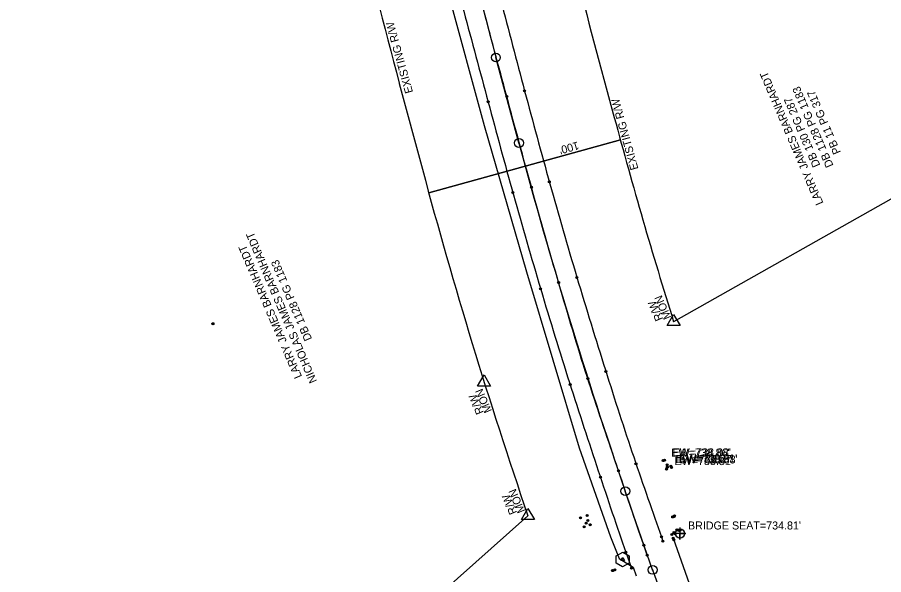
# Model space of a CAD drawing. Extents: x 1550153 to 1552579, y 809637 to 812160.
# Drawn here: x 1551459.6 to 1551894.8, y 810857.2 to 811136.9 of the extents above; entities that cross this region are included whole.
import ezdxf

# ---------------------------------------------------------------- set-up
doc = ezdxf.new("R2010")
doc.units = 0
for name, color, linetype in [('CTL Primary Horizontal and Vertical CELL', 7, 'Continuous'), ('Default', 7, 'Continuous'), ('E_NCDOT_Horizontal_Alignment', 7, 'Continuous'), ('E_NCDOT_Horizontal_Alignment_Curve', 7, 'Continuous'), ('E_NCDOT_Horizontal_Alignment_Tick_Label', 7, 'Continuous'), ('Exist DTM Crownline', 7, 'Continuous'), ('Exist Property Text', 7, 'Continuous'), ('Exist Right of Way Line', 7, 'Continuous'), ('Exist Right of Way Line Leader', 7, 'Continuous'), ('Exist Right of Way Line Text', 7, 'Continuous'), ('Exist Right of Way Monument CELL', 7, 'Continuous'), ('Exist Right of Way Monument Text', 7, 'Continuous'), ('Exist Roads EOP', 7, 'Continuous'), ('Exist Roads EOP Other', 7, 'Continuous'), ('Exist Structure Major Bridge Seat Cogo Point CELL', 7, 'Continuous'), ('Exist Structure Minor Head and End Wall', 7, 'Continuous'), ('Exist Survey Control Group', 7, 'Continuous'), ('Exist Utilities Telephone UG Cable SUE LOS B', 7, 'Continuous')]:
    doc.layers.add(name, color=color, linetype=linetype)

# ---------------------------------------------------------------- blocks, each defined once
blk = doc.blocks.new('SurveyPointCell')
at = {"layer": 'Default'}
for p, q in [((-0.5, 0), (0.5, 0)), ((0, -0.5), (0, 0.5))]:
    blk.add_line(p, q, dxfattribs=at)
blk.add_circle((0, 0), 0.5, dxfattribs=at)
blk = doc.blocks.new('SurveyControlPointCell')
at = {"layer": 'Default'}
for p, q in [((-0.87, -0.5), (0, 1)), ((0, 1), (0.87, -0.5)), ((0.87, -0.5), (-0.87, -0.5))]:
    blk.add_line(p, q, dxfattribs=at)
blk.add_circle((0, 0), 0.5, dxfattribs=at)

msp = doc.modelspace()

# ---------------------------------------------------------------- linework, layer by layer
at = {"layer": 'CTL Primary Horizontal and Vertical CELL'}
msp.add_line((1551763.72, 810864.75), (1551763.72, 810864.75), dxfattribs=at)
msp.add_line((1551763.72, 810864.75), (1551763.72, 810864.75), dxfattribs=at)
msp.add_line((1551763.72, 810864.75), (1551763.72, 810864.75), dxfattribs=at)
msp.add_lwpolyline([(1551760.49, 810866.62), (1551763.74, 810868.43), (1551766.99, 810866.65), (1551766.94, 810862.92), (1551763.69, 810861.03), (1551760.49, 810862.85)], close=True, dxfattribs=at)
msp.add_lwpolyline([(1551760.49, 810866.62), (1551763.74, 810868.43), (1551766.99, 810866.65), (1551766.94, 810862.92), (1551763.69, 810861.03), (1551760.49, 810862.85)], close=True, dxfattribs=at)
msp.add_lwpolyline([(1551760.49, 810866.62), (1551763.74, 810868.43), (1551766.99, 810866.65), (1551766.94, 810862.92), (1551763.69, 810861.03), (1551760.49, 810862.85)], close=True, dxfattribs=at)
at = {"layer": 'Default'}
for p, q in [((1551792.49, 810877.81), (1551792.49, 810877.81)), ((1551763.72, 810864.75), (1551763.72, 810864.75))]:
    msp.add_line(p, q, dxfattribs=at)
msp.add_arc((1544558.52, 818987.58), 11000, 308.905285, 313.48368, dxfattribs=at)
msp.add_arc((1544558.52, 818987.58), 11000, 308.905285, 313.48368, dxfattribs=at)
at = {"layer": 'E_NCDOT_Horizontal_Alignment'}
for p, q in [((1551711.61, 811073.81), (1551700.02, 811116.69)), ((1551778.76, 810859.54), (1551765.03, 810899.04))]:
    msp.add_line(p, q, dxfattribs=at)
for centre, radius in [((1551700.02, 811116.69), 2.2), ((1551700.02, 811116.69), 0.0707), ((1551711.61, 811073.81), 2.2), ((1551711.61, 811073.81), 0.0707), ((1551765.03, 810899.04), 2.2), ((1551765.03, 810899.04), 0.0707), ((1551778.76, 810859.54), 2.2), ((1551778.76, 810859.54), 0.0707)]:
    msp.add_circle(centre, radius, dxfattribs=at)
at = {"layer": 'E_NCDOT_Horizontal_Alignment_Curve'}
for centre, radius, start, end in [((1571051.3, 816169.19), 20000, 194.057496, 194.632887), ((1571051.3, 816169.19), 20000, 194.057496, 194.632887), ((1554271.06, 811760.59), 2650, 195.02047, 198.97242), ((1554271.06, 811760.59), 2650, 195.02047, 198.97242), ((1544245.73, 819324.67), 11459.16, 307.933611, 313.133611), ((1544245.73, 819324.67), 11459.16, 307.933611, 313.133611), ((1554277.17, 811742.97), 2650, 199.47344, 205.4841), ((1554277.17, 811742.97), 2650, 199.47344, 205.4841)]:
    msp.add_arc(centre, radius, start, end, dxfattribs=at)
at = {"layer": 'E_NCDOT_Horizontal_Alignment_Tick_Label'}
msp.add_arc((1544558.52, 818987.58), 11000, 308.905285, 313.48368, dxfattribs=at)
at = {"layer": 'Exist DTM Crownline'}
msp.add_line((1551775.98, 810866.94), (1551774.27, 810871.88), dxfattribs=at)
msp.add_line((1551775.98, 810866.94), (1551774.27, 810871.88), dxfattribs=at)
msp.add_open_spline([(1551774.27, 810871.88), (1551769.96, 810884.28), (1551760.75, 810912.22), (1551745.66, 810955.91), (1551731.5, 811003.54), (1551718, 811050.78), (1551705.43, 811097.26), (1551693.24, 811142.67), (1551681.43, 811187.98), (1551670.2, 811231.95), (1551663.06, 811260.98), (1551659.56, 811274.89)], degree=3, dxfattribs=at)
msp.add_open_spline([(1551774.27, 810871.88), (1551769.96, 810884.28), (1551760.75, 810912.22), (1551745.66, 810955.91), (1551731.5, 811003.54), (1551718, 811050.78), (1551705.43, 811097.26), (1551693.24, 811142.67), (1551681.43, 811187.98), (1551670.2, 811231.95), (1551663.06, 811260.98), (1551659.56, 811274.89)], degree=3, dxfattribs=at)
at = {"layer": 'Exist Right of Way Line'}
for p, q in [((1551965.65, 811083.67), (1551789.31, 810984.03)), ((1551716.1, 810886.69), (1551186.17, 810416.44))]:
    msp.add_line(p, q, dxfattribs=at)
for points in [[(1551747.95, 811129.4), (1551759.49, 811086.68), (1551759.5, 811086.64)], [(1551651.41, 811103.86), (1551651.46, 811103.65), (1551663.1, 811060.6)]]:
    msp.add_lwpolyline(points, dxfattribs=at)
for centre, radius, start, end in [((1571051.08, 816168.98), 20050, 194.120183, 194.632887), ((1571050.91, 816169.06), 19950, 194.207218, 194.632275), ((1554270.67, 811760.47), 2600, 195.02047, 197.37538), ((1554270.83, 811760.39), 2700, 195.02141, 198.88035)]:
    msp.add_arc(centre, radius, start, end, dxfattribs=at)
at = {"layer": 'Exist Right of Way Line Leader'}
for p, q in [((1551666.29, 811048.77), (1551762.55, 811075.38)), ((1551762.55, 811075.38), (1551666.29, 811048.77))]:
    msp.add_line(p, q, dxfattribs=at)
at = {"layer": 'Exist Right of Way Monument CELL'}
for p, q in [((1551789.31, 810984.03), (1551789.31, 810984.03)), ((1551789.31, 810984.03), (1551789.31, 810984.03)), ((1551694.04, 810953.63), (1551694.04, 810953.63)), ((1551694.04, 810953.63), (1551694.04, 810953.63)), ((1551716.1, 810886.69), (1551716.1, 810886.69)), ((1551716.1, 810886.69), (1551716.1, 810886.69))]:
    msp.add_line(p, q, dxfattribs=at)
for points in [[(1551786.06, 810982.14), (1551789.31, 810987.78), (1551792.56, 810982.14)], [(1551786.06, 810982.14), (1551789.31, 810987.78), (1551792.56, 810982.14)], [(1551690.79, 810951.74), (1551694.04, 810957.38), (1551697.29, 810951.74)], [(1551690.79, 810951.74), (1551694.04, 810957.38), (1551697.29, 810951.74)], [(1551712.86, 810884.8), (1551716.11, 810890.44), (1551719.35, 810884.8)], [(1551712.86, 810884.8), (1551716.11, 810890.44), (1551719.35, 810884.8)]]:
    msp.add_lwpolyline(points, close=True, dxfattribs=at)
at = {"layer": 'Exist Roads EOP'}
for p, q in [((1551783.17, 810876.09), (1551783.92, 810873.92)), ((1551783.17, 810876.09), (1551783.92, 810873.92)), ((1551765.29, 810868.44), (1551768.13, 810860.38)), ((1551765.29, 810868.44), (1551768.13, 810860.38))]:
    msp.add_line(p, q, dxfattribs=at)
for points in [[(1551669.23, 811277), (1551672.74, 811263.65), (1551679.61, 811234.96), (1551690.37, 811191.22), (1551702.41, 811145.66), (1551714.33, 811100.03), (1551727, 811053.46), (1551740.47, 811006.5), (1551755.13, 810959.34), (1551769.1, 810915.85), (1551778.93, 810888.33), (1551783.17, 810876.09)], [(1551669.23, 811277), (1551672.74, 811263.65), (1551679.61, 811234.96), (1551690.37, 811191.22), (1551702.41, 811145.66), (1551714.33, 811100.03), (1551727, 811053.46), (1551740.47, 811006.5), (1551755.13, 810959.34), (1551769.1, 810915.85), (1551778.93, 810888.33), (1551783.17, 810876.09)], [(1551650.09, 811272.18), (1551653.54, 811258.38), (1551661.25, 811229.54), (1551671.78, 811185.41), (1551683.85, 811140.03), (1551696.07, 811094.57), (1551708.62, 811047.91), (1551722.36, 811000.57), (1551736.98, 810952.93), (1551751.55, 810908.96), (1551760.88, 810880.93), (1551765.29, 810868.44)], [(1551650.09, 811272.18), (1551653.54, 811258.38), (1551661.25, 811229.54), (1551671.78, 811185.41), (1551683.85, 811140.03), (1551696.07, 811094.57), (1551708.62, 811047.91), (1551722.36, 811000.57), (1551736.98, 810952.93), (1551751.55, 810908.96), (1551760.88, 810880.93), (1551765.29, 810868.44)]]:
    msp.add_open_spline(points, degree=3, dxfattribs=at)
at = {"layer": 'Exist Roads EOP Other'}
msp.add_line((1551789.07, 810875.41), (1551799.93, 810844.99), dxfattribs=at)
msp.add_line((1551789.07, 810875.41), (1551799.93, 810844.99), dxfattribs=at)
at = {"layer": 'Exist Structure Major Bridge Seat Cogo Point CELL'}
msp.add_lwpolyline([(1551792.49, 810880.81), (1551792.49, 810874.81), (1551792.49, 810877.81), (1551795.49, 810877.81), (1551789.49, 810877.81)], dxfattribs=at)
msp.add_circle((1551792.49, 810877.81), 2.34, dxfattribs=at)
at = {"layer": 'Exist Survey Control Group'}
msp.add_line((1551763.72, 810864.75), (1551763.72, 810864.75), dxfattribs=at)
msp.add_lwpolyline([(1551762.85, 810864.25), (1551763.72, 810865.75), (1551764.58, 810864.25)], close=True, dxfattribs=at)
msp.add_circle((1551763.72, 810864.75), 0.5, dxfattribs=at)
at = {"layer": 'Exist Utilities Telephone UG Cable SUE LOS B'}
msp.add_lwpolyline([(1551635.47, 811205.41), (1551654.84, 811204.95), (1551659.43, 811203.7), (1551662.57, 811201.11), (1551675.9, 811149.68), (1551694.16, 811082.62), (1551715.46, 811009.19), (1551741.91, 810920.73), (1551757.61, 810876.2), (1551761.94, 810865.34), (1551769.04, 810860.85), (1551770.5, 810856.61)], dxfattribs=at)

# ---------------------------------------------------------------- block references
at = {"layer": 'Default'}
for name, p in [('SurveyPointCell', (1551705.47, 811097.19)), ('SurveyPointCell', (1551705.47, 811097.19)), ('SurveyPointCell', (1551714.44, 811099.93)), ('SurveyPointCell', (1551714.44, 811099.93)), ('SurveyPointCell', (1551696.08, 811094.54)), ('SurveyPointCell', (1551696.08, 811094.54)), ('SurveyPointCell', (1551726.86, 811054.37)), ('SurveyPointCell', (1551726.86, 811054.37)), ('SurveyPointCell', (1551708.51, 811048.9)), ('SurveyPointCell', (1551708.51, 811048.9)), ('SurveyPointCell', (1551717.87, 811051.66)), ('SurveyPointCell', (1551717.87, 811051.66)), ('SurveyPointCell', (1551740.71, 811006.35)), ('SurveyPointCell', (1551740.71, 811006.35)), ('SurveyPointCell', (1551722.47, 811000.64)), ('SurveyPointCell', (1551722.47, 811000.64)), ('SurveyPointCell', (1551731.53, 811003.74)), ('SurveyPointCell', (1551731.53, 811003.74)), ('SurveyPointCell', (1551557.89, 810983.12)), ('SurveyPointCell', (1551557.89, 810983.12)), ('SurveyPointCell', (1551755.26, 810959.19)), ('SurveyPointCell', (1551755.26, 810959.19)), ('SurveyPointCell', (1551737.3, 810952.53)), ('SurveyPointCell', (1551737.3, 810952.53)), ('SurveyPointCell', (1551746.16, 810955.54)), ('SurveyPointCell', (1551746.16, 810955.54)), ('SurveyPointCell', (1551784.09, 810914.38)), ('SurveyPointCell', (1551784.09, 810914.38)), ('SurveyPointCell', (1551784.74, 810914.55)), ('SurveyPointCell', (1551784.74, 810914.55)), ('SurveyPointCell', (1551761.66, 810909.21)), ('SurveyPointCell', (1551761.66, 810909.21)), ('SurveyPointCell', (1551770.39, 810912.78)), ('SurveyPointCell', (1551770.39, 810912.78)), ('SurveyPointCell', (1551785.74, 810910.15)), ('SurveyPointCell', (1551785.74, 810910.15)), ('SurveyPointCell', (1551786.05, 810912.31)), ('SurveyPointCell', (1551786.05, 810912.31)), ('SurveyPointCell', (1551786.12, 810911.12)), ('SurveyPointCell', (1551786.12, 810911.12)), ('SurveyPointCell', (1551787.94, 810911.59)), ('SurveyPointCell', (1551787.94, 810911.59)), ('SurveyPointCell', (1551788.17, 810910.96)), ('SurveyPointCell', (1551788.17, 810910.96)), ('SurveyPointCell', (1551752.52, 810906.06)), ('SurveyPointCell', (1551752.52, 810906.06)), ('SurveyPointCell', (1551745.83, 810886.87)), ('SurveyPointCell', (1551745.83, 810886.87)), ('SurveyPointCell', (1551742.47, 810885.7)), ('SurveyPointCell', (1551742.47, 810885.7)), ('SurveyPointCell', (1551745.35, 810883.06)), ('SurveyPointCell', (1551745.35, 810883.06)), ('SurveyPointCell', (1551746.14, 810884.32)), ('SurveyPointCell', (1551746.14, 810884.32)), ('SurveyPointCell', (1551788.83, 810886.11)), ('SurveyPointCell', (1551788.83, 810886.11)), ('SurveyPointCell', (1551789.49, 810886.35)), ('SurveyPointCell', (1551789.49, 810886.35)), ('SurveyPointCell', (1551789.72, 810886.68)), ('SurveyPointCell', (1551789.72, 810886.68)), ('SurveyPointCell', (1551744.32, 810881.11)), ('SurveyPointCell', (1551744.32, 810881.11)), ('SurveyPointCell', (1551747.39, 810882.23)), ('SurveyPointCell', (1551747.39, 810882.23)), ('SurveyPointCell', (1551789.5, 810878.31)), ('SurveyPointCell', (1551789.5, 810878.31)), ('SurveyPointCell', (1551790.96, 810879.6)), ('SurveyPointCell', (1551790.96, 810879.6)), ('SurveyPointCell', (1551791.97, 810879.37)), ('SurveyPointCell', (1551791.97, 810879.37)), ('SurveyPointCell', (1551792.5, 810879.49)), ('SurveyPointCell', (1551792.5, 810879.49)), ('SurveyPointCell', (1551783.17, 810876.09)), ('SurveyPointCell', (1551783.17, 810876.09)), ('SurveyPointCell', (1551783.92, 810873.92)), ('SurveyPointCell', (1551783.92, 810873.92)), ('SurveyPointCell', (1551788.44, 810877.26)), ('SurveyPointCell', (1551788.44, 810877.26)), ('SurveyPointCell', (1551789.07, 810875.41)), ('SurveyPointCell', (1551789.07, 810875.41)), ('SurveyPointCell', (1551789.38, 810874.58)), ('SurveyPointCell', (1551789.38, 810874.58)), ('SurveyPointCell', (1551790.09, 810877.72)), ('SurveyPointCell', (1551790.09, 810877.72)), ('SurveyPointCell', (1551774.27, 810871.88)), ('SurveyPointCell', (1551774.27, 810871.88)), ('SurveyControlPointCell', (1551763.72, 810864.75)), ('SurveyControlPointCell', (1551763.72, 810864.75)), ('SurveyPointCell', (1551765.29, 810868.44)), ('SurveyPointCell', (1551765.29, 810868.44)), ('SurveyPointCell', (1551775.98, 810866.94)), ('SurveyPointCell', (1551775.98, 810866.94)), ('SurveyPointCell', (1551758.54, 810859.17)), ('SurveyPointCell', (1551758.54, 810859.17)), ('SurveyPointCell', (1551758.96, 810859.29)), ('SurveyPointCell', (1551758.96, 810859.29)), ('SurveyPointCell', (1551759.76, 810859.53)), ('SurveyPointCell', (1551759.76, 810859.53)), ('SurveyPointCell', (1551768.13, 810860.38)), ('SurveyPointCell', (1551768.13, 810860.38))]:
    msp.add_blockref(name, p, dxfattribs=at)

# ---------------------------------------------------------------- texts
msp.add_text("BRIDGE SEAT=734.81'", height=4.02, dxfattribs=at).set_placement((1551796.51, 810879.82))
at = {"layer": 'Exist Property Text'}
for s, p in [('LARRY JAMES BARNHARDT', (1551864.63, 811043.64)), ('DB 1128 PG 1183', (1551869.67, 811062.51)), ('PB 11 PG 317', (1551873.39, 811069.14)), ('DB 130 PG 287', (1551863.06, 811062.63)), ('NICHOLAS JAMES BARNHARDT', (1551610.25, 810954.29)), ('LARRY JAMES BARNHARDT', (1551602.7, 810956.6)), ('DB 1128 PG 1183', (1551607.74, 810975.48))]:
    msp.add_text(s, height=4.02, rotation=113.1736, dxfattribs=at).set_placement(p)
at = {"layer": 'Exist Right of Way Line Text'}
for s, rotation, p in [('EXISTING R/W', 105.4318, (1551658.41, 811099.32)), ('EXISTING R/W', 105.4712, (1551771.65, 811060.85)), ("100'", 195.347, (1551741.09, 811074.6))]:
    msp.add_text(s, height=4.02, rotation=rotation, dxfattribs=at).set_placement(p)
at = {"layer": 'Exist Right of Way Monument Text'}
for s, p in [('MON', (1551788.15, 810986.24)), ('R/W', (1551784.08, 810985.47)), ('MON', (1551698.11, 810939.37)), ('R/W', (1551694.04, 810938.6)), ('R/W', (1551710.74, 810888.32)), ('MON', (1551714.81, 810889.09))]:
    msp.add_text(s, height=4.02, rotation=113.1736, dxfattribs=at).set_placement(p)
at = {"layer": 'Exist Structure Minor Head and End Wall'}
for s, p in [("EW=738.86'", (1551788.11, 810916.39)), ("EW=738.88'", (1551788.76, 810916.56)), ("EW=738.81'", (1551789.76, 810912.16)), ("EW=738.87'", (1551790.14, 810913.13)), ("EW=738.81'", (1551791.96, 810913.6)), ("EW=738.88'", (1551792.19, 810912.97))]:
    msp.add_text(s, height=4.02, dxfattribs=at).set_placement(p)

doc.saveas('drawing.dxf')
